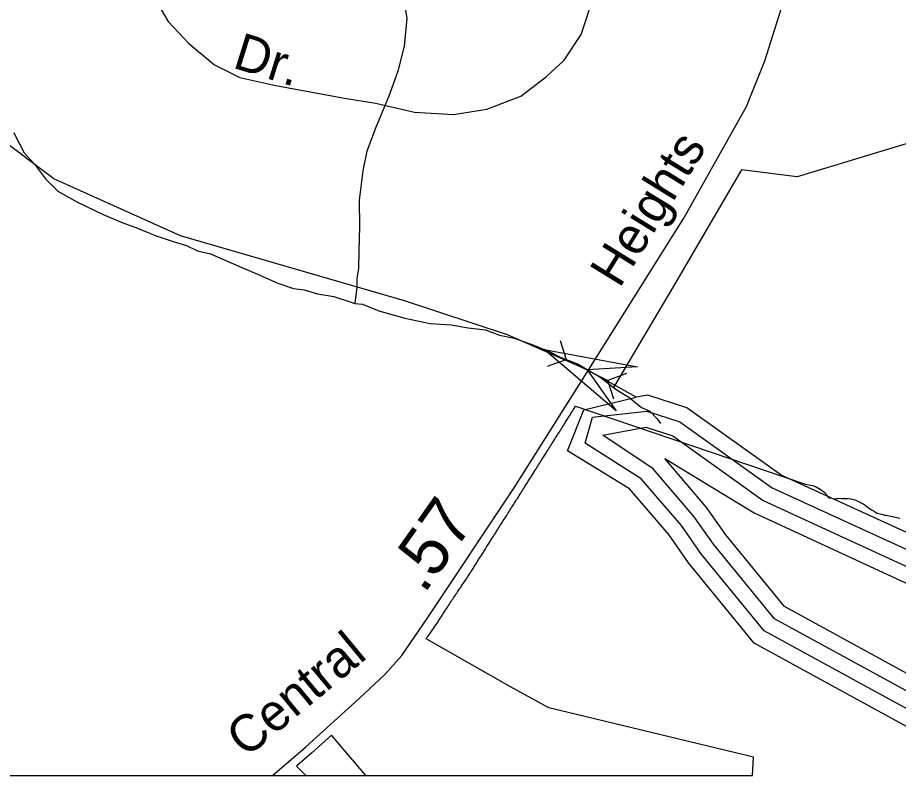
# Model space of a CAD drawing. Extents: x 2315291 to 2336543, y 597177 to 615230.
# Drawn here: x 2325292 to 2327561, y 597530 to 599483 of the extents above; entities that cross this region are included whole.
import ezdxf

# ---------------------------------------------------------------- set-up
doc = ezdxf.new("R2010")
doc.units = 0
for name, color, linetype in [('Exist Boundary Political City Limit New', 7, 'Continuous'), ('Exist Hydrographic Buffer Line', 7, 'Continuous'), ('Exist Hydrographic Creek Single Shore', 7, 'Continuous'), ('Exist Hydrographic Lake Shore', 7, 'Continuous'), ('Exist Hydrographic Misc Water Feature', 7, 'Continuous'), ('Exist Road Non-System Type 51', 7, 'Continuous'), ('Exist Road Non-System Type 51 Label', 7, 'Continuous'), ('Exist Road Secondary Mileage Hundredths English Label', 7, 'Continuous'), ('Exist Road Secondary Structure Pipe Attributed CELL', 7, 'Continuous'), ('Exist Road Secondary Structure Pipe CELL', 7, 'Continuous'), ('Exist Road Secondary Type 51 Attributed', 7, 'Continuous'), ('Exist Road Secondary Type 51 Label', 7, 'Continuous'), ('Map Preparation Boundary City Limit Buffer Line', 7, 'Continuous')]:
    doc.layers.add(name, color=color, linetype=linetype)

msp = doc.modelspace()

# ---------------------------------------------------------------- linework, layer by layer
at = {"layer": 'Exist Boundary Political City Limit New'}
msp.add_line((2326034.2, 597529.5), (2326189.3, 597529.5), dxfattribs=at)
for points in [[(2315744.5, 604723.7), (2315744.5, 597529.5), (2327185.3, 597529.5)], [(2326620, 598308.1), (2326622.8, 598312.4), (2326625.5, 598316.5), (2326627.5, 598319.9), (2326629.8, 598323.2), (2326631.8, 598326.6), (2326634.2, 598330.3), (2326636.2, 598333.4), (2326638.2, 598336.8), (2326640.5, 598340.2), (2326642.5, 598343.6), (2326644.5, 598346.8), (2326646.8, 598350.3), (2326649, 598353.8), (2326651.2, 598357.1), (2326653.2, 598360.5), (2326654.8, 598363), (2326656.5, 598365.6), (2326658.5, 598368.8), (2326660.8, 598372.4), (2326662.8, 598375.6), (2326665, 598379.2), (2326667, 598382.5), (2326669.2, 598385.8), (2326670.8, 598388.4), (2326672.5, 598390.9), (2326674, 598393.4), (2326675.8, 598396), (2326677.8, 598399.4), (2326680, 598402.8), (2326682, 598406.2), (2326684, 598409.4), (2326686.2, 598412.9), (2326688.5, 598416.3), (2326690.5, 598419.8), (2326692.8, 598423.1), (2326695, 598426.8), (2326697, 598429.9), (2326699, 598433.2), (2326701.2, 598436.6), (2326702.8, 598439.2), (2326704.5, 598441.7), (2326706, 598444.2), (2326707.5, 598446.8), (2326709.8, 598450.2), (2326711.2, 598452.8), (2326713, 598455.2), (2326715, 598458.4), (2326717.2, 598462.1), (2326719.2, 598465.4), (2326721.5, 598468.8), (2326723.5, 598472.2), (2326725.8, 598475.7), (2326727.2, 598478.3), (2326727.8, 598478.8), (2326729.2, 598481.5), (2327322, 598280.2), (2327325.2, 598279.3), (2327331.2, 598278.3), (2327335.2, 598277.5), (2327339, 598276.6), (2327342, 598275.8), (2327344.8, 598275), (2327347.8, 598273.9), (2327352, 598271.8), (2327355.5, 598269.8), (2327359.2, 598267.8), (2327363.2, 598265.2), (2327365.8, 598263.1), (2327368.8, 598260.5), (2327371.8, 598257.9), (2327374.2, 598254.9), (2327376.2, 598252.4), (2327378.8, 598247.9), (2327383.2, 598244.9), (2327386.8, 598244.8), (2327391.2, 598243.2), (2327397.2, 598242.9), (2327401.2, 598243), (2327405.8, 598243), (2327410.8, 598243.8), (2327415.2, 598243.3), (2327419.5, 598243.5), (2327425.5, 598243.6), (2327431.2, 598243.1), (2327438.2, 598242.2), (2327441.2, 598241.8), (2327444.2, 598241.2), (2327449, 598239.7), (2327452.8, 598238.3), (2327456.2, 598236.9), (2327460.8, 598234.9), (2327463.2, 598233.4), (2327466.8, 598231.3), (2327470, 598229.2), (2327475.2, 598225.9), (2327479.8, 598222.6), (2327483.2, 598220.2)], [(2326432, 598012.5), (2326434.2, 598015.8), (2326435.8, 598018.3), (2326437.5, 598020.8), (2326439.8, 598024.2), (2326442, 598027.4), (2326444.2, 598030.6), (2326444.8, 598031.4), (2326445.2, 598032.2), (2326447.5, 598035.8), (2326449.8, 598039), (2326452, 598042.3), (2326453.8, 598044.9), (2326455.5, 598047.7), (2326457.8, 598051.1), (2326459.8, 598054.6), (2326462, 598057.9), (2326463.5, 598060.4), (2326465.2, 598062.9), (2326467.2, 598066.3), (2326470, 598070.7), (2326472, 598073.9), (2326473.8, 598076.4), (2326475.8, 598079.8), (2326478.5, 598084.2), (2326481.2, 598088.3), (2326483.2, 598091.7), (2326485.5, 598095), (2326487.5, 598098.4), (2326489.2, 598100.9), (2326490.8, 598103.5), (2326492.8, 598106.8), (2326494.5, 598109.4), (2326496.2, 598112), (2326498.2, 598115.4), (2326500.2, 598118.7), (2326502.5, 598122.1), (2326504, 598124.5), (2326505.8, 598127.2), (2326507.5, 598129.7), (2326509, 598132.2), (2326510.5, 598134.8), (2326512.2, 598137.5), (2326514.2, 598140.7), (2326516.5, 598144.1), (2326518.5, 598147.4), (2326520.8, 598150.8), (2326523.5, 598155.1), (2326526, 598159.3), (2326528.2, 598162.7), (2326530.2, 598166.1), (2326532.5, 598169.3), (2326534.5, 598172.8), (2326536.8, 598176.2), (2326538.2, 598178.8), (2326540, 598181.2), (2326542.2, 598184.8), (2326543.8, 598187.2), (2326545.2, 598189.7), (2326547.5, 598193.1), (2326549.5, 598196.5), (2326551.8, 598199.9), (2326553.8, 598203.1), (2326556, 598206.7), (2326558.2, 598210), (2326560.2, 598213.5), (2326562.5, 598216.8), (2326564.5, 598220.1), (2326566.8, 598223.5), (2326568.2, 598226.1), (2326570, 598228.6), (2326571.5, 598231.1), (2326572, 598231.9), (2326572.5, 598232.8), (2326575.2, 598237.1), (2326577.5, 598240.4), (2326579.5, 598243.6), (2326581.2, 598246.3), (2326582.8, 598248.9), (2326584.2, 598251.4), (2326586, 598253.9), (2326588, 598257.3), (2326590.2, 598260.7), (2326592.5, 598264.1), (2326594.5, 598267.5), (2326596.8, 598271), (2326598.8, 598274.2), (2326600.5, 598276.8), (2326602, 598279.3), (2326603.5, 598281.8), (2326605.2, 598284.4), (2326607.2, 598287.8), (2326609, 598290.2), (2326610.5, 598292.8), (2326612, 598295.4), (2326613.8, 598297.9), (2326615.2, 598300.4), (2326617, 598303), (2326618.5, 598305.5), (2326620, 598308.1)], [(2327483.2, 598220.2), (2327486.5, 598217.8), (2327490.5, 598214.9), (2327493, 598213.2), (2327496.5, 598211.2), (2327501.8, 598208.1), (2327506.2, 598205.9), (2327510, 598204.8), (2327513.8, 598203.8), (2327517.8, 598202.8), (2327521, 598201.9), (2327526, 598200.8), (2327529.5, 598200.1), (2327533.2, 598199.2), (2327537.2, 598198.4), (2327541.2, 598197.6), (2327545, 598196.8), (2327549, 598196.1), (2327553.5, 598195.2), (2327556.8, 598194.4), (2327560.8, 598193.6), (2327564.8, 598192.6)], [(2326427.2, 598005.6), (2326429.8, 598009.2), (2326432, 598012.5)], [(2327185.3, 597529.5), (2327187.8, 597576.2), (2326660.2, 597703.4), (2326561.5, 597757.9), (2326344, 597881.4), (2326346.2, 597884.6), (2326348.8, 597887.7), (2326351, 597891), (2326353.2, 597894), (2326355.2, 597896.7), (2326357, 597899.3), (2326359.2, 597902.4), (2326361, 597905), (2326363.2, 597908.1), (2326366, 597912.2), (2326368.2, 597915.6), (2326370.5, 597918.9), (2326372.8, 597922.2), (2326375, 597925.6), (2326376.5, 597928.1), (2326378.2, 597930.6), (2326379.8, 597933.1), (2326381.5, 597935.6), (2326383.5, 597939), (2326385.2, 597941.6), (2326386.8, 597944.1), (2326389, 597947.4), (2326391.5, 597951.8), (2326393.8, 597955.1), (2326395.2, 597957.6), (2326397.5, 597960.9), (2326399.8, 597964.5), (2326401.8, 597967.4), (2326404.2, 597971), (2326406.2, 597974.3), (2326408.5, 597977.6), (2326410.8, 597980.9), (2326413, 597984.2), (2326415.2, 597987.6), (2326417.5, 597990.9), (2326419.8, 597994.2), (2326421.2, 597996.8), (2326423, 597999.2), (2326425.2, 598002.6), (2326427.2, 598005.6)], [(2326189.3, 597529.5), (2326100.2, 597633), (2326050, 597587.9), (2326010.2, 597553.2), (2326034.2, 597529.5)]]:
    msp.add_lwpolyline(points, dxfattribs=at)
at = {"layer": 'Exist Hydrographic Buffer Line'}
for points in [[(2327876.1, 597659.7), (2327603.6, 597689.7), (2327215.4, 597902.1), (2327052.4, 598101.4), (2327002.2, 598173.5), (2326898.6, 598294.2), (2326753.7, 598385.8), (2326773.2, 598452.7), (2326913, 598468.3), (2326998.1, 598441.3), (2327236.2, 598271), (2327736.7, 598041), (2328045.1, 597974.9), (2328605.7, 598006.2), (2329044.5, 598120.1), (2329557.1, 598323.3), (2329691.7, 598323.1), (2329718.9, 598234.2), (2329746, 598032.9), (2329707.7, 597843.9), (2329688, 597789), (2329618.7, 597723.2), (2329559, 597704.8), (2327876.1, 597659.7)], [(2327877.8, 597699.7), (2327615.9, 597728.6), (2327241.5, 597933.5), (2327084.4, 598125.5), (2327035.2, 598196.3), (2326929.2, 598320.2), (2326799.2, 598406.7), (2326910.1, 598427.2), (2326980, 598405), (2327213, 598238.5), (2327720.1, 598004.6), (2328036.9, 597935.8), (2328608.2, 597966.2), (2329054.8, 598081.4), (2329564.7, 598283.3), (2329676.3, 598283.2), (2329679.4, 598227.9), (2329705.4, 598034.3), (2329669.1, 597854.7), (2329653.7, 597811.4), (2329597.9, 597758.7), (2329552.4, 597744.7), (2327877.8, 597699.7)], [(2327879.4, 597739.8), (2327628.2, 597767.5), (2327267.3, 597964.8), (2327116.2, 598149.6), (2327067.8, 598219.2), (2326959.3, 598346.3), (2327189.6, 598206), (2327703.5, 597968.2), (2328028.7, 597896.6), (2328610.4, 597926.3), (2329064.6, 598042.6), (2329572.5, 598243.3), (2329635.9, 598243.1), (2329665, 598035.6), (2329630.3, 597865.5), (2329577.2, 597794.1), (2327879.4, 597739.8)]]:
    msp.add_lwpolyline(points, dxfattribs=at)
at = {"layer": 'Exist Hydrographic Creek Single Shore'}
msp.add_lwpolyline([(2326885.5, 598504.4), (2326758.8, 598574.9), (2326553.6, 598665.4), (2326288.4, 598753.2), (2325711.4, 598920.2), (2325385.4, 599067.9), (2325242.4, 599173.7)], dxfattribs=at)
at = {"layer": 'Exist Hydrographic Lake Shore'}
for points in [[(2329786.4, 598031.6), (2329758.5, 598240.5), (2329741.5, 598331.7), (2329707.4, 598363.1), (2329549.4, 598363.3), (2329034.5, 598158.7), (2328603.4, 598046.1), (2328053.5, 598014.1), (2327753.5, 598077.4), (2327259.3, 598303.5), (2327016.3, 598477.5), (2326915.5, 598509.5), (2326885.5, 598504.4)], [(2329786.4, 598031.6), (2329746.4, 597833.1), (2329722.4, 597766.4), (2329639.4, 597687.7), (2329565.3, 597664.9), (2327874.5, 597619.6), (2327591.5, 597650.8), (2327189.4, 597870.8), (2327020.4, 598077.3), (2326969.4, 598150.7), (2326868.5, 598268.1), (2326708.4, 598366.6), (2326750.7, 598472.2), (2326885.5, 598504.4)]]:
    msp.add_lwpolyline(points, dxfattribs=at)
at = {"layer": 'Exist Hydrographic Misc Water Feature'}
for points in [[(2326289.8, 599513.1), (2326294.4, 599481.2), (2326287.6, 599409.3), (2326271.8, 599345.1), (2326248.6, 599280.9), (2326215.8, 599202.7), (2326191.8, 599138.6), (2326181, 599088.3), (2326171.7, 599012.2), (2326172.3, 598944.4), (2326170.9, 598882.2), (2326169.7, 598836.2), (2326165.8, 598810.4), (2326166, 598788.5), (2326160.7, 598746.3)], [(2328154.8, 599347.3), (2327730.9, 599203), (2327300.3, 599072.4), (2327156.4, 599090.8), (2326981.5, 598791), (2326826.7, 598529.7)], [(2325282.2, 599186.6), (2325284.3, 599180.7), (2325308.5, 599134.9), (2325335.1, 599105.3), (2325363.6, 599067.8), (2325395.8, 599036.1), (2325444.4, 599008.6), (2325512.3, 598975.2), (2325558.8, 598955.6), (2325600.9, 598940), (2325649.1, 598920.6), (2325692.7, 598905.5), (2325727.2, 598895.4), (2325755.3, 598881.9), (2325789.1, 598874.3), (2325855.7, 598844.9), (2325910.1, 598821.7), (2325961.8, 598798.1), (2326002.2, 598784.7), (2326029.8, 598780.9), (2326064.1, 598771.4), (2326106.1, 598763.8), (2326148.6, 598750.1), (2326160.7, 598746.3)], [(2326160.7, 598746.3), (2326180.3, 598744.5), (2326222.4, 598726.9), (2326289, 598707.9), (2326354.6, 598694.4), (2326409, 598691.1), (2326452.9, 598683.6), (2326496.9, 598677.9), (2326533.2, 598664.2), (2326571.2, 598656.9), (2326619.2, 598639.2), (2326663.4, 598621.9), (2326689.7, 598607.9), (2326734, 598590.7), (2326792.2, 598557.2), (2326822.2, 598533.5), (2326826.7, 598529.7)], [(2326826.7, 598529.7), (2326840.8, 598519.8), (2326866.7, 598504.2), (2326898.8, 598478.2), (2326921, 598468.8), (2326939.4, 598448.6), (2326947.7, 598436.8)]]:
    msp.add_lwpolyline(points, dxfattribs=at)
at = {"layer": 'Exist Road Non-System Type 51'}
msp.add_lwpolyline([(2325634, 599551.2), (2325679.6, 599473.3), (2325732.8, 599416.2), (2325799.3, 599361.1), (2325863.9, 599328.8), (2325957.1, 599307.8), (2326133.8, 599275.5), (2326213.6, 599262.2), (2326314.3, 599239.4), (2326415, 599233.7), (2326500.6, 599247), (2326588, 599280.3), (2326654.5, 599331.6), (2326700.1, 599373.5), (2326743.8, 599440), (2326776.1, 599538.9)], dxfattribs=at)
at = {"layer": 'Exist Road Secondary Structure Pipe Attributed CELL'}
msp.add_lwpolyline([(2326834.2, 598469), (2326648.7, 598627.3), (2326888.5, 598583), (2326758.8, 598574.9)], close=True, dxfattribs=at)
at = {"layer": 'Exist Road Secondary Structure Pipe CELL'}
for p, q in [((2326689.9, 598650.5), (2326704.7, 598601.9)), ((2326657, 598584.6), (2326704.7, 598601.9)), ((2326704.7, 598601.9), (2326812.8, 598547.8)), ((2326860.5, 598565.2), (2326812.8, 598547.8)), ((2326827.6, 598499.2), (2326812.8, 598547.8))]:
    msp.add_line(p, q, dxfattribs=at)
at = {"layer": 'Exist Road Secondary Type 51 Attributed'}
msp.add_lwpolyline([(2325948.1, 597529.5), (2326033.1, 597602.2), (2326171.8, 597727.7), (2326238.3, 597789.5), (2326282, 597838.9), (2326346.6, 597934), (2326570.9, 598270.6), (2326778, 598599.5), (2327008, 598966.5), (2327169.5, 599253.7), (2327217, 599371.6), (2327262.6, 599516.1), (2327289.2, 599632.1), (2327302.5, 599698.6), (2327312, 599759.5), (2327342.4, 600000), (2327394.7, 600474)], dxfattribs=at)
at = {"layer": 'Map Preparation Boundary City Limit Buffer Line'}
msp.add_line((2326034.2, 597529.5), (2326189.3, 597529.5), dxfattribs=at)
for points in [[(2315744.5, 604723.7), (2315744.5, 597529.5), (2327185.3, 597529.5)], [(2326620, 598308.1), (2326622.8, 598312.4), (2326625.5, 598316.5), (2326627.5, 598319.9), (2326629.8, 598323.2), (2326631.8, 598326.6), (2326634.2, 598330.3), (2326636.2, 598333.4), (2326638.2, 598336.8), (2326640.5, 598340.2), (2326642.5, 598343.6), (2326644.5, 598346.8), (2326646.8, 598350.3), (2326649, 598353.8), (2326651.2, 598357.1), (2326653.2, 598360.5), (2326654.8, 598363), (2326656.5, 598365.6), (2326658.5, 598368.8), (2326660.8, 598372.4), (2326662.8, 598375.6), (2326665, 598379.2), (2326667, 598382.5), (2326669.2, 598385.8), (2326670.8, 598388.4), (2326672.5, 598390.9), (2326674, 598393.4), (2326675.8, 598396), (2326677.8, 598399.4), (2326680, 598402.8), (2326682, 598406.2), (2326684, 598409.4), (2326686.2, 598412.9), (2326688.5, 598416.3), (2326690.5, 598419.8), (2326692.8, 598423.1), (2326695, 598426.8), (2326697, 598429.9), (2326699, 598433.2), (2326701.2, 598436.6), (2326702.8, 598439.2), (2326704.5, 598441.7), (2326706, 598444.2), (2326707.5, 598446.8), (2326709.8, 598450.2), (2326711.2, 598452.8), (2326713, 598455.2), (2326715, 598458.4), (2326717.2, 598462.1), (2326719.2, 598465.4), (2326721.5, 598468.8), (2326723.5, 598472.2), (2326725.8, 598475.7), (2326727.2, 598478.3), (2326727.8, 598478.8), (2326729.2, 598481.5), (2327322, 598280.2), (2327325.2, 598279.3), (2327331.2, 598278.3), (2327335.2, 598277.5), (2327339, 598276.6), (2327342, 598275.8), (2327344.8, 598275), (2327347.8, 598273.9), (2327352, 598271.8), (2327355.5, 598269.8), (2327359.2, 598267.8), (2327363.2, 598265.2), (2327365.8, 598263.1), (2327368.8, 598260.5), (2327371.8, 598257.9), (2327374.2, 598254.9), (2327376.2, 598252.4), (2327378.8, 598247.9), (2327383.2, 598244.9), (2327386.8, 598244.8), (2327391.2, 598243.2), (2327397.2, 598242.9), (2327401.2, 598243), (2327405.8, 598243), (2327410.8, 598243.8), (2327415.2, 598243.3), (2327419.5, 598243.5), (2327425.5, 598243.6), (2327431.2, 598243.1), (2327438.2, 598242.2), (2327441.2, 598241.8), (2327444.2, 598241.2), (2327449, 598239.7), (2327452.8, 598238.3), (2327456.2, 598236.9), (2327460.8, 598234.9), (2327463.2, 598233.4), (2327466.8, 598231.3), (2327470, 598229.2), (2327475.2, 598225.9), (2327479.8, 598222.6), (2327483.2, 598220.2)], [(2326432, 598012.5), (2326434.2, 598015.8), (2326435.8, 598018.3), (2326437.5, 598020.8), (2326439.8, 598024.2), (2326442, 598027.4), (2326444.2, 598030.6), (2326444.8, 598031.4), (2326445.2, 598032.2), (2326447.5, 598035.8), (2326449.8, 598039), (2326452, 598042.3), (2326453.8, 598044.9), (2326455.5, 598047.7), (2326457.8, 598051.1), (2326459.8, 598054.6), (2326462, 598057.9), (2326463.5, 598060.4), (2326465.2, 598062.9), (2326467.2, 598066.3), (2326470, 598070.7), (2326472, 598073.9), (2326473.8, 598076.4), (2326475.8, 598079.8), (2326478.5, 598084.2), (2326481.2, 598088.3), (2326483.2, 598091.7), (2326485.5, 598095), (2326487.5, 598098.4), (2326489.2, 598100.9), (2326490.8, 598103.5), (2326492.8, 598106.8), (2326494.5, 598109.4), (2326496.2, 598112), (2326498.2, 598115.4), (2326500.2, 598118.7), (2326502.5, 598122.1), (2326504, 598124.5), (2326505.8, 598127.2), (2326507.5, 598129.7), (2326509, 598132.2), (2326510.5, 598134.8), (2326512.2, 598137.5), (2326514.2, 598140.7), (2326516.5, 598144.1), (2326518.5, 598147.4), (2326520.8, 598150.8), (2326523.5, 598155.1), (2326526, 598159.3), (2326528.2, 598162.7), (2326530.2, 598166.1), (2326532.5, 598169.3), (2326534.5, 598172.8), (2326536.8, 598176.2), (2326538.2, 598178.8), (2326540, 598181.2), (2326542.2, 598184.8), (2326543.8, 598187.2), (2326545.2, 598189.7), (2326547.5, 598193.1), (2326549.5, 598196.5), (2326551.8, 598199.9), (2326553.8, 598203.1), (2326556, 598206.7), (2326558.2, 598210), (2326560.2, 598213.5), (2326562.5, 598216.8), (2326564.5, 598220.1), (2326566.8, 598223.5), (2326568.2, 598226.1), (2326570, 598228.6), (2326571.5, 598231.1), (2326572, 598231.9), (2326572.5, 598232.8), (2326575.2, 598237.1), (2326577.5, 598240.4), (2326579.5, 598243.6), (2326581.2, 598246.3), (2326582.8, 598248.9), (2326584.2, 598251.4), (2326586, 598253.9), (2326588, 598257.3), (2326590.2, 598260.7), (2326592.5, 598264.1), (2326594.5, 598267.5), (2326596.8, 598271), (2326598.8, 598274.2), (2326600.5, 598276.8), (2326602, 598279.3), (2326603.5, 598281.8), (2326605.2, 598284.4), (2326607.2, 598287.8), (2326609, 598290.2), (2326610.5, 598292.8), (2326612, 598295.4), (2326613.8, 598297.9), (2326615.2, 598300.4), (2326617, 598303), (2326618.5, 598305.5), (2326620, 598308.1)], [(2327483.2, 598220.2), (2327486.5, 598217.8), (2327490.5, 598214.9), (2327493, 598213.2), (2327496.5, 598211.2), (2327501.8, 598208.1), (2327506.2, 598205.9), (2327510, 598204.8), (2327513.8, 598203.8), (2327517.8, 598202.8), (2327521, 598201.9), (2327526, 598200.8), (2327529.5, 598200.1), (2327533.2, 598199.2), (2327537.2, 598198.4), (2327541.2, 598197.6), (2327545, 598196.8), (2327549, 598196.1), (2327553.5, 598195.2), (2327556.8, 598194.4), (2327560.8, 598193.6), (2327564.8, 598192.6)], [(2326427.2, 598005.6), (2326429.8, 598009.2), (2326432, 598012.5)], [(2327185.3, 597529.5), (2327187.8, 597576.2), (2326660.2, 597703.4), (2326561.5, 597757.9), (2326344, 597881.4), (2326346.2, 597884.6), (2326348.8, 597887.7), (2326351, 597891), (2326353.2, 597894), (2326355.2, 597896.7), (2326357, 597899.3), (2326359.2, 597902.4), (2326361, 597905), (2326363.2, 597908.1), (2326366, 597912.2), (2326368.2, 597915.6), (2326370.5, 597918.9), (2326372.8, 597922.2), (2326375, 597925.6), (2326376.5, 597928.1), (2326378.2, 597930.6), (2326379.8, 597933.1), (2326381.5, 597935.6), (2326383.5, 597939), (2326385.2, 597941.6), (2326386.8, 597944.1), (2326389, 597947.4), (2326391.5, 597951.8), (2326393.8, 597955.1), (2326395.2, 597957.6), (2326397.5, 597960.9), (2326399.8, 597964.5), (2326401.8, 597967.4), (2326404.2, 597971), (2326406.2, 597974.3), (2326408.5, 597977.6), (2326410.8, 597980.9), (2326413, 597984.2), (2326415.2, 597987.6), (2326417.5, 597990.9), (2326419.8, 597994.2), (2326421.2, 597996.8), (2326423, 597999.2), (2326425.2, 598002.6), (2326427.2, 598005.6)], [(2326189.3, 597529.5), (2326100.2, 597633), (2326050, 597587.9), (2326010.2, 597553.2), (2326034.2, 597529.5)]]:
    msp.add_lwpolyline(points, dxfattribs=at)

# ---------------------------------------------------------------- texts
at = {"layer": 'Exist Road Non-System Type 51 Label'}
msp.add_text('Dr.', height=95, rotation=342.6387, dxfattribs=at).set_placement((2325842.9, 599354.9))
at = {"layer": 'Exist Road Secondary Mileage Hundredths English Label'}
msp.add_text('.57', height=125, rotation=54.7899, dxfattribs=at).set_placement((2326339, 597995))
at = {"layer": 'Exist Road Secondary Type 51 Label'}
for s, rotation, p in [('Heights', 58.3668, (2326842.6, 598783.2)), ('Central', 39.6123, (2325880.3, 597572.8))]:
    msp.add_text(s, height=95, rotation=rotation, dxfattribs=at).set_placement(p)

doc.saveas('drawing.dxf')
